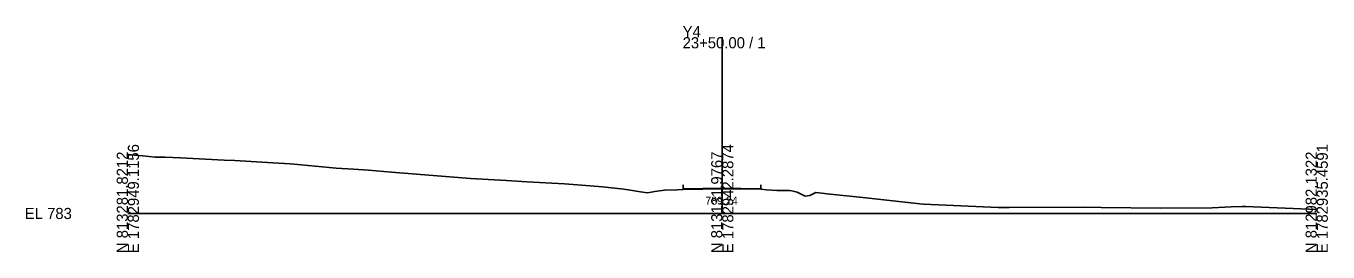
# Model space of a CAD drawing. Extents: x -26 to 3903, y -10 to 9562.
# Drawn here: x 3574.3 to 3902.8, y -9.7 to 47.2 of the extents above; entities that cross this region are included whole.
import ezdxf

# ---------------------------------------------------------------- set-up
doc = ezdxf.new("R2010")
doc.units = 0
for name, color, linetype in [('Exist Cross Section Cell', 7, 'Continuous'), ('Exist XS Center Line Elevation Label', 7, 'Continuous'), ('Exist XS Ground Line', 7, 'Continuous'), ('Prop XS EOT Tick Mark', 7, 'Continuous'), ('Prop XS Finish Grade Pavement', 7, 'Continuous')]:
    doc.layers.add(name, color=color, linetype=linetype)

msp = doc.modelspace()

# ---------------------------------------------------------------- linework, layer by layer
at = {"layer": 'Exist Cross Section Cell'}
for p, q in [((3750, 0), (3750, 44.43)), ((3600, 0), (3750, 0)), ((3750, 0), (3900, 0))]:
    msp.add_line(p, q, dxfattribs=at)
at = {"layer": 'Exist XS Ground Line'}
for p, q in [((3600, 14.81), (3600.84, 14.76)), ((3600.84, 14.76), (3602.47, 14.62)), ((3602.47, 14.62), (3603.66, 14.54)), ((3603.66, 14.54), (3606.85, 14.15)), ((3606.85, 14.15), (3609.34, 14.17)), ((3609.34, 14.17), (3613.32, 14)), ((3613.32, 14), (3624.28, 13.44)), ((3624.28, 13.44), (3627.01, 13.34)), ((3627.01, 13.34), (3636.61, 12.75)), ((3636.61, 12.75), (3637.98, 12.68)), ((3637.98, 12.68), (3639.49, 12.59)), ((3639.49, 12.59), (3640.92, 12.47)), ((3640.92, 12.47), (3641.94, 12.42)), ((3641.94, 12.42), (3652.54, 11.43)), ((3652.54, 11.43), (3656.98, 11.14)), ((3656.98, 11.14), (3660.7, 10.88)), ((3660.7, 10.88), (3666.49, 10.38)), ((3666.49, 10.38), (3686.43, 8.85)), ((3686.43, 8.85), (3695.59, 8.31)), ((3695.59, 8.31), (3700.7, 7.99)), ((3700.7, 7.99), (3710.19, 7.48)), ((3710.19, 7.48), (3716.7, 7)), ((3716.7, 7), (3719.8, 6.68)), ((3719.8, 6.68), (3725.15, 6.13)), ((3725.15, 6.13), (3727.34, 5.83)), ((3727.34, 5.83), (3729.37, 5.44)), ((3729.37, 5.44), (3731.15, 5.18)), ((3731.15, 5.18), (3732.94, 5.51)), ((3732.94, 5.51), (3735.38, 5.9)), ((3735.38, 5.9), (3738.56, 5.99)), ((3738.56, 5.99), (3740.11, 6.06)), ((3740.11, 6.06), (3745.07, 6.14)), ((3745.07, 6.14), (3750.04, 6.24)), ((3750.04, 6.24), (3754.66, 6.18)), ((3754.66, 6.18), (3759.74, 6.12)), ((3759.74, 6.12), (3761.14, 5.93)), ((3761.14, 5.93), (3763.77, 5.78)), ((3763.77, 5.78), (3766.99, 5.8)), ((3766.99, 5.8), (3767.57, 5.69)), ((3767.57, 5.69), (3768.92, 5.4)), ((3768.92, 5.4), (3770.95, 4.39)), ((3770.95, 4.39), (3772.06, 4.51)), ((3772.06, 4.51), (3773.57, 5.26)), ((3773.57, 5.26), (3777.26, 4.88)), ((3777.26, 4.88), (3785.46, 4.05)), ((3785.46, 4.05), (3799.89, 2.42)), ((3799.89, 2.42), (3800.77, 2.32)), ((3800.77, 2.32), (3819.61, 1.54)), ((3819.61, 1.54), (3822.37, 1.47)), ((3822.37, 1.47), (3841.17, 1.56)), ((3841.17, 1.56), (3845.64, 1.54)), ((3845.64, 1.54), (3860.67, 1.31)), ((3860.67, 1.31), (3873.63, 1.46)), ((3873.63, 1.46), (3878.44, 1.71)), ((3878.44, 1.71), (3881.23, 1.75)), ((3881.23, 1.75), (3881.77, 1.77)), ((3881.77, 1.77), (3882.07, 1.78)), ((3882.07, 1.78), (3900, 0.96))]:
    msp.add_line(p, q, dxfattribs=at)
at = {"layer": 'Prop XS EOT Tick Mark'}
for p, q in [((3740.11, 6.19), (3740.11, 7.19)), ((3759.74, 6.24), (3759.74, 7.24))]:
    msp.add_line(p, q, dxfattribs=at)
at = {"layer": 'Prop XS Finish Grade Pavement'}
for p, q in [((3740.11, 6.19), (3745.06, 6.27)), ((3745.06, 6.27), (3750.04, 6.37)), ((3750.04, 6.37), (3754.66, 6.3)), ((3754.66, 6.3), (3759.74, 6.24))]:
    msp.add_line(p, q, dxfattribs=at)

# ---------------------------------------------------------------- texts
at = {"layer": 'Exist Cross Section Cell'}
for s, p in [('Y4', (3740, 44.43)), ('23+50.00 / 1', (3740, 41.63)), ('EL 783', (3574, -1.4))]:
    msp.add_text(s, height=2.8, dxfattribs=at).set_placement(p)
for s, p in [('E 1782949.1156', (3602.8, -10)), ('E 1782942.2874', (3752.8, -10)), ('E 1782935.4591', (3902.8, -10)), ('N 813281.8212', (3600, -10)), ('N 813131.9767', (3750, -10)), ('N 812982.1322', (3900, -10))]:
    msp.add_text(s, height=2.8, rotation=90, dxfattribs=at).set_placement(p)
at = {"layer": 'Exist XS Center Line Elevation Label'}
msp.add_text('789.24', height=2, dxfattribs=at).set_placement((3745.72, 2.24))

doc.saveas('drawing.dxf')
